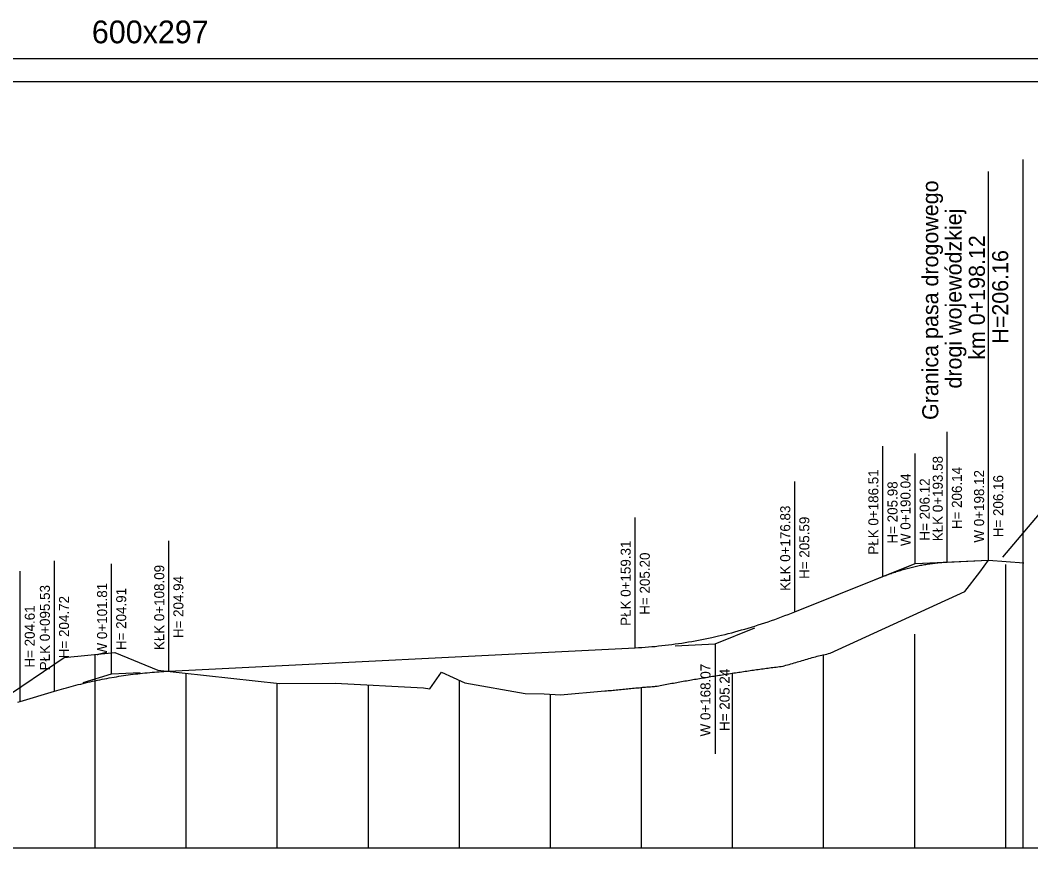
# Model space of a CAD drawing. Extents: x 6513080 to 6513380, y 6022307 to 6022459.
# Drawn here: x 6513209.5 to 6513320.4, y 6022367.8 to 6022459.5 of the extents above; entities that cross this region are included whole.
import ezdxf

# ---------------------------------------------------------------- set-up
doc = ezdxf.new("R2010")
doc.units = 0
for name, color, linetype in [('1', 7, 'Continuous'), ('42', 7, 'Continuous'), ('CONSTRUCTION_CLASS', 7, 'Continuous'), ('maxp_opisy', 7, 'Continuous'), ('maxp_ramka_2', 7, 'Continuous')]:
    doc.layers.add(name, color=color, linetype=linetype)

msp = doc.modelspace()

# ---------------------------------------------------------------- linework, layer by layer
for p, q in [((6513294.53, 6022394.49), (6513307.74, 6022399.78)), ((6513307.74, 6022399.78), (6513315.82, 6022400.17)), ((6513311.28, 6022399.95), (6513315.82, 6022400.17)), ((6513294.53, 6022394.49), (6513304.21, 6022398.37)), ((6513225.79, 6022387.98), (6513277.01, 6022390.55)), ((6513225.79, 6022387.98), (6513277.01, 6022390.55)), ((6513209.47, 6022384.65), (6513213.23, 6022385.78)), ((6513209.47, 6022384.65), (6513213.23, 6022385.78))]:
    msp.add_line(p, q)
for points in [[(6513304.21, 6022398.37), (6513304.36, 6022398.43), (6513304.51, 6022398.49), (6513304.65, 6022398.54), (6513304.8, 6022398.6), (6513304.95, 6022398.65), (6513305.1, 6022398.7), (6513305.24, 6022398.76), (6513305.39, 6022398.81), (6513305.54, 6022398.86), (6513305.68, 6022398.91), (6513305.83, 6022398.95), (6513305.98, 6022399), (6513306.13, 6022399.04), (6513306.27, 6022399.09), (6513306.42, 6022399.13), (6513306.57, 6022399.17), (6513306.71, 6022399.22), (6513306.86, 6022399.26), (6513307.01, 6022399.29), (6513307.16, 6022399.33), (6513307.3, 6022399.37), (6513307.45, 6022399.4), (6513307.6, 6022399.44), (6513307.89, 6022399.51), (6513308.04, 6022399.54), (6513308.19, 6022399.57), (6513308.33, 6022399.6), (6513308.48, 6022399.62), (6513308.63, 6022399.65), (6513308.78, 6022399.68), (6513308.92, 6022399.7), (6513309.07, 6022399.73), (6513309.22, 6022399.75), (6513309.36, 6022399.77), (6513309.51, 6022399.79), (6513309.66, 6022399.81), (6513309.81, 6022399.83), (6513309.95, 6022399.84), (6513310.1, 6022399.86), (6513310.25, 6022399.88), (6513310.39, 6022399.89), (6513310.54, 6022399.9), (6513310.69, 6022399.91), (6513310.84, 6022399.93), (6513310.98, 6022399.94), (6513311.13, 6022399.94), (6513311.28, 6022399.95)], [(6513277.01, 6022390.55), (6513277.38, 6022390.57), (6513277.74, 6022390.59), (6513278.11, 6022390.61), (6513278.47, 6022390.64), (6513278.84, 6022390.67), (6513279.2, 6022390.7), (6513279.57, 6022390.74), (6513279.93, 6022390.78), (6513280.3, 6022390.82), (6513280.66, 6022390.86), (6513281.03, 6022390.91), (6513281.39, 6022390.96), (6513281.76, 6022391.01), (6513282.12, 6022391.06), (6513282.49, 6022391.12), (6513282.85, 6022391.18), (6513283.22, 6022391.24), (6513283.58, 6022391.31), (6513283.95, 6022391.37), (6513284.31, 6022391.44), (6513284.68, 6022391.52), (6513285.04, 6022391.59), (6513285.41, 6022391.67), (6513286.14, 6022391.84), (6513286.5, 6022391.92), (6513286.87, 6022392.01), (6513287.23, 6022392.1), (6513287.6, 6022392.2), (6513287.96, 6022392.29), (6513288.33, 6022392.39), (6513288.69, 6022392.5), (6513289.06, 6022392.6), (6513289.42, 6022392.71), (6513289.79, 6022392.82), (6513290.15, 6022392.93), (6513290.52, 6022393.05), (6513290.88, 6022393.16), (6513291.25, 6022393.29), (6513291.61, 6022393.41), (6513291.98, 6022393.54), (6513292.34, 6022393.66), (6513292.71, 6022393.8), (6513293.07, 6022393.93), (6513293.44, 6022394.07), (6513293.8, 6022394.21), (6513294.17, 6022394.35), (6513294.53, 6022394.49)], [(6513277.01, 6022390.55), (6513277.38, 6022390.57), (6513277.74, 6022390.59), (6513278.11, 6022390.61), (6513278.47, 6022390.64), (6513278.84, 6022390.67), (6513279.2, 6022390.7), (6513279.57, 6022390.74), (6513279.93, 6022390.78), (6513280.3, 6022390.82), (6513280.66, 6022390.86), (6513281.03, 6022390.91), (6513281.39, 6022390.96), (6513281.76, 6022391.01), (6513282.12, 6022391.06), (6513282.49, 6022391.12), (6513282.85, 6022391.18), (6513283.22, 6022391.24), (6513283.58, 6022391.31), (6513283.95, 6022391.37), (6513284.31, 6022391.44), (6513284.68, 6022391.52), (6513285.04, 6022391.59), (6513285.41, 6022391.67), (6513286.14, 6022391.84), (6513286.5, 6022391.92), (6513286.87, 6022392.01), (6513287.23, 6022392.1), (6513287.6, 6022392.2), (6513287.96, 6022392.29), (6513288.33, 6022392.39), (6513288.69, 6022392.5), (6513289.06, 6022392.6), (6513289.42, 6022392.71), (6513289.79, 6022392.82), (6513290.15, 6022392.93), (6513290.52, 6022393.05), (6513290.88, 6022393.16), (6513291.25, 6022393.29), (6513291.61, 6022393.41), (6513291.98, 6022393.54), (6513292.34, 6022393.66), (6513292.71, 6022393.8), (6513293.07, 6022393.93), (6513293.44, 6022394.07), (6513293.8, 6022394.21), (6513294.17, 6022394.35), (6513294.53, 6022394.49)], [(6513213.23, 6022385.78), (6513213.49, 6022385.86), (6513213.75, 6022385.93), (6513214.01, 6022386.01), (6513214.27, 6022386.08), (6513214.54, 6022386.15), (6513214.8, 6022386.23), (6513215.06, 6022386.3), (6513215.32, 6022386.36), (6513215.58, 6022386.43), (6513215.84, 6022386.5), (6513216.11, 6022386.56), (6513216.37, 6022386.62), (6513216.63, 6022386.69), (6513216.89, 6022386.75), (6513217.15, 6022386.81), (6513217.41, 6022386.86), (6513217.68, 6022386.92), (6513217.94, 6022386.97), (6513218.2, 6022387.03), (6513218.46, 6022387.08), (6513218.72, 6022387.13), (6513218.98, 6022387.18), (6513219.25, 6022387.23), (6513219.77, 6022387.32), (6513220.03, 6022387.36), (6513220.29, 6022387.41), (6513220.55, 6022387.45), (6513220.82, 6022387.49), (6513221.08, 6022387.53), (6513221.34, 6022387.56), (6513221.6, 6022387.6), (6513221.86, 6022387.63), (6513222.12, 6022387.67), (6513222.39, 6022387.7), (6513222.65, 6022387.73), (6513222.91, 6022387.76), (6513223.17, 6022387.78), (6513223.43, 6022387.81), (6513223.69, 6022387.83), (6513223.96, 6022387.86), (6513224.22, 6022387.88), (6513224.48, 6022387.9), (6513224.74, 6022387.92), (6513225, 6022387.94), (6513225.26, 6022387.95), (6513225.53, 6022387.97), (6513225.79, 6022387.98)], [(6513213.23, 6022385.78), (6513213.49, 6022385.86), (6513213.75, 6022385.93), (6513214.01, 6022386.01), (6513214.27, 6022386.08), (6513214.54, 6022386.15), (6513214.8, 6022386.23), (6513215.06, 6022386.3), (6513215.32, 6022386.36), (6513215.58, 6022386.43), (6513215.84, 6022386.5), (6513216.11, 6022386.56), (6513216.37, 6022386.62), (6513216.63, 6022386.69), (6513216.89, 6022386.75), (6513217.15, 6022386.81), (6513217.41, 6022386.86), (6513217.68, 6022386.92), (6513217.94, 6022386.97), (6513218.2, 6022387.03), (6513218.46, 6022387.08), (6513218.72, 6022387.13), (6513218.98, 6022387.18), (6513219.25, 6022387.23), (6513219.77, 6022387.32), (6513220.03, 6022387.36), (6513220.29, 6022387.41), (6513220.55, 6022387.45), (6513220.82, 6022387.49), (6513221.08, 6022387.53), (6513221.34, 6022387.56), (6513221.6, 6022387.6), (6513221.86, 6022387.63), (6513222.12, 6022387.67), (6513222.39, 6022387.7), (6513222.65, 6022387.73), (6513222.91, 6022387.76), (6513223.17, 6022387.78), (6513223.43, 6022387.81), (6513223.69, 6022387.83), (6513223.96, 6022387.86), (6513224.22, 6022387.88), (6513224.48, 6022387.9), (6513224.74, 6022387.92), (6513225, 6022387.94), (6513225.26, 6022387.95), (6513225.53, 6022387.97), (6513225.79, 6022387.98)], [(6513209.21, 6022384.57), (6513209.47, 6022384.65)], [(6513209.21, 6022384.57), (6513209.47, 6022384.65)]]:
    msp.add_lwpolyline(points)
at = {"layer": '1'}
for p, q in [((6513305.98, 6022399.08), (6513307.74, 6022399.78)), ((6513307.74, 6022399.78), (6513309.51, 6022399.87)), ((6513315.82, 6022400.17), (6513319.69, 6022399.86)), ((6513317.7, 6022368.56), (6513317.7, 6022399.68)), ((6513285.77, 6022390.98), (6513290.15, 6022392.74)), ((6513307.7, 6022368.56), (6513307.7, 6022392.05)), ((6513281.39, 6022390.77), (6513285.77, 6022390.98)), ((6513217.7, 6022368.56), (6513217.7, 6022389.82)), ((6513297.7, 6022368.56), (6513297.7, 6022389.79)), ((6513216.37, 6022386.72), (6513219.51, 6022387.67)), ((6513219.51, 6022387.67), (6513222.65, 6022387.83)), ((6513227.7, 6022368.56), (6513227.7, 6022387.76)), ((6513287.7, 6022368.56), (6513287.7, 6022387.76)), ((6513237.7, 6022368.56), (6513237.7, 6022386.66)), ((6513247.7, 6022368.56), (6513247.7, 6022386.46)), ((6513257.7, 6022368.56), (6513257.7, 6022386.96)), ((6513277.7, 6022368.56), (6513277.7, 6022386.19)), ((6513267.7, 6022368.56), (6513267.7, 6022385.43)), ((6513217.7, 6022368.56), (6513217.7, 6022370.56)), ((6513227.7, 6022368.56), (6513227.7, 6022369.56)), ((6513237.7, 6022368.56), (6513237.7, 6022369.56)), ((6513247.7, 6022368.56), (6513247.7, 6022369.56)), ((6513257.7, 6022368.56), (6513257.7, 6022369.56)), ((6513267.7, 6022368.56), (6513267.7, 6022369.56)), ((6513277.7, 6022368.56), (6513277.7, 6022369.56)), ((6513287.7, 6022368.56), (6513287.7, 6022369.56)), ((6513297.7, 6022368.56), (6513297.7, 6022369.56)), ((6513307.7, 6022368.56), (6513307.7, 6022369.56)), ((6513317.7, 6022368.56), (6513317.7, 6022370.56)), ((6513117.7, 6022368.56), (6513327.7, 6022368.56))]:
    msp.add_line(p, q, dxfattribs=at)
msp.add_lwpolyline([(6513207.39, 6022384.79), (6513214.28, 6022389.47), (6513219.87, 6022390.04), (6513224.57, 6022388.1), (6513237.96, 6022386.63), (6513244.04, 6022386.65), (6513253.74, 6022386.15), (6513254.46, 6022386.02), (6513255.73, 6022387.88), (6513258.29, 6022386.69), (6513264.93, 6022385.53), (6513267.02, 6022385.47), (6513268.82, 6022385.37), (6513273.67, 6022385.81), (6513273.85, 6022385.82), (6513274.03, 6022385.84), (6513274.21, 6022385.85), (6513274.39, 6022385.87), (6513274.57, 6022385.89), (6513274.75, 6022385.9), (6513274.93, 6022385.92), (6513275.11, 6022385.94), (6513275.29, 6022385.95), (6513275.46, 6022385.97), (6513275.64, 6022385.99), (6513275.82, 6022386), (6513276, 6022386.02), (6513276.18, 6022386.04), (6513276.36, 6022386.06), (6513276.54, 6022386.07), (6513276.72, 6022386.09), (6513276.9, 6022386.11), (6513277.08, 6022386.13), (6513277.26, 6022386.14), (6513277.44, 6022386.16), (6513277.61, 6022386.18), (6513277.79, 6022386.2), (6513277.97, 6022386.22), (6513278.15, 6022386.23), (6513278.28, 6022386.25), (6513278.33, 6022386.25), (6513278.51, 6022386.26), (6513278.69, 6022386.27), (6513278.87, 6022386.28), (6513279.05, 6022386.29), (6513279.14, 6022386.29), (6513279.23, 6022386.31), (6513279.41, 6022386.34), (6513279.59, 6022386.38), (6513279.76, 6022386.41), (6513279.94, 6022386.44), (6513280.12, 6022386.48), (6513280.3, 6022386.51), (6513280.48, 6022386.54), (6513280.66, 6022386.58), (6513280.84, 6022386.61), (6513281.02, 6022386.64), (6513281.2, 6022386.67), (6513281.38, 6022386.71), (6513281.56, 6022386.74), (6513281.74, 6022386.77), (6513281.91, 6022386.8), (6513282.09, 6022386.83), (6513282.27, 6022386.87), (6513282.45, 6022386.9), (6513282.63, 6022386.93), (6513282.81, 6022386.96), (6513282.99, 6022386.99), (6513283.17, 6022387.02), (6513283.35, 6022387.05), (6513283.53, 6022387.08), (6513283.71, 6022387.11), (6513283.89, 6022387.14), (6513284.06, 6022387.17), (6513284.24, 6022387.2), (6513284.42, 6022387.23), (6513284.6, 6022387.26), (6513284.78, 6022387.29), (6513284.96, 6022387.32), (6513285.14, 6022387.35), (6513285.32, 6022387.38), (6513285.5, 6022387.41), (6513285.68, 6022387.44), (6513285.86, 6022387.47), (6513286.04, 6022387.5), (6513286.22, 6022387.53), (6513286.39, 6022387.55), (6513286.57, 6022387.58), (6513286.75, 6022387.61), (6513286.93, 6022387.64), (6513287.11, 6022387.67), (6513287.29, 6022387.69), (6513287.47, 6022387.72), (6513287.65, 6022387.75), (6513287.83, 6022387.78), (6513288.01, 6022387.8), (6513288.19, 6022387.83), (6513288.37, 6022387.86), (6513288.54, 6022387.88), (6513288.72, 6022387.91), (6513288.9, 6022387.94), (6513289.08, 6022387.96), (6513289.26, 6022387.99), (6513289.44, 6022388.01), (6513289.62, 6022388.04), (6513289.8, 6022388.07), (6513289.98, 6022388.09), (6513290.16, 6022388.12), (6513290.34, 6022388.14), (6513290.52, 6022388.17), (6513290.69, 6022388.19), (6513290.87, 6022388.22), (6513291.05, 6022388.24), (6513291.23, 6022388.26), (6513291.41, 6022388.29), (6513291.59, 6022388.31), (6513291.77, 6022388.34), (6513291.95, 6022388.36), (6513292.13, 6022388.38), (6513292.31, 6022388.41), (6513292.49, 6022388.43), (6513292.67, 6022388.45), (6513292.84, 6022388.47), (6513293.02, 6022388.5), (6513293.2, 6022388.52), (6513293.27, 6022388.53), (6513293.38, 6022388.56), (6513293.56, 6022388.62), (6513293.74, 6022388.67), (6513293.92, 6022388.72), (6513294.1, 6022388.78), (6513294.28, 6022388.83), (6513294.46, 6022388.88), (6513294.64, 6022388.94), (6513294.82, 6022388.99), (6513294.99, 6022389.04), (6513295.17, 6022389.09), (6513295.35, 6022389.15), (6513295.53, 6022389.2), (6513295.71, 6022389.25), (6513295.89, 6022389.3), (6513296.07, 6022389.35), (6513296.25, 6022389.41), (6513296.43, 6022389.46), (6513296.61, 6022389.51), (6513296.79, 6022389.56), (6513296.97, 6022389.61), (6513297.14, 6022389.66), (6513297.3, 6022389.7), (6513297.32, 6022389.71), (6513297.5, 6022389.75), (6513297.68, 6022389.78), (6513297.86, 6022389.82), (6513298.04, 6022389.86), (6513298.22, 6022389.9), (6513298.4, 6022389.94), (6513313.2, 6022396.72), (6513314.86, 6022398.86), (6513315.82, 6022400.17)], dxfattribs=at)
at = {"layer": '42'}
for p, q in [((6513319.62, 6022368.56), (6513319.62, 6022444.15)), ((6513315.82, 6022400.17), (6513315.82, 6022442.86)), ((6513311.28, 6022399.95), (6513311.28, 6022414.25)), ((6513304.21, 6022398.37), (6513304.21, 6022412.67)), ((6513307.74, 6022399.78), (6513307.74, 6022411.88)), ((6513315.82, 6022400.17), (6513315.82, 6022412.27)), ((6513294.53, 6022394.49), (6513294.53, 6022408.79)), ((6513323.46, 6022407.75), (6513317.33, 6022400.48)), ((6513277.01, 6022390.55), (6513277.01, 6022404.85)), ((6513225.79, 6022387.98), (6513225.79, 6022402.28)), ((6513213.23, 6022385.78), (6513213.23, 6022400.08)), ((6513219.51, 6022387.67), (6513219.51, 6022399.77)), ((6513311.28, 6022399.95), (6513315.82, 6022400.17)), ((6513209.47, 6022384.65), (6513209.47, 6022398.95)), ((6513294.53, 6022394.49), (6513304.21, 6022398.37)), ((6513285.77, 6022390.98), (6513285.77, 6022378.88)), ((6513225.79, 6022387.98), (6513277.01, 6022390.55)), ((6513209.47, 6022384.65), (6513213.23, 6022385.78))]:
    msp.add_line(p, q, dxfattribs=at)
for points in [[(6513304.21, 6022398.37), (6513304.36, 6022398.43), (6513304.51, 6022398.49), (6513304.65, 6022398.54), (6513304.8, 6022398.6), (6513304.95, 6022398.65), (6513305.1, 6022398.7), (6513305.24, 6022398.76), (6513305.39, 6022398.81), (6513305.54, 6022398.86), (6513305.68, 6022398.91), (6513305.83, 6022398.95), (6513305.98, 6022399), (6513306.13, 6022399.04), (6513306.27, 6022399.09), (6513306.42, 6022399.13), (6513306.57, 6022399.17), (6513306.71, 6022399.22), (6513306.86, 6022399.26), (6513307.01, 6022399.29), (6513307.16, 6022399.33), (6513307.3, 6022399.37), (6513307.45, 6022399.4), (6513307.6, 6022399.44), (6513307.89, 6022399.51), (6513308.04, 6022399.54), (6513308.19, 6022399.57), (6513308.33, 6022399.6), (6513308.48, 6022399.62), (6513308.63, 6022399.65), (6513308.78, 6022399.68), (6513308.92, 6022399.7), (6513309.07, 6022399.73), (6513309.22, 6022399.75), (6513309.36, 6022399.77), (6513309.51, 6022399.79), (6513309.66, 6022399.81), (6513309.81, 6022399.83), (6513309.95, 6022399.84), (6513310.1, 6022399.86), (6513310.25, 6022399.88), (6513310.39, 6022399.89), (6513310.54, 6022399.9), (6513310.69, 6022399.91), (6513310.84, 6022399.93), (6513310.98, 6022399.94), (6513311.13, 6022399.94), (6513311.28, 6022399.95)], [(6513277.01, 6022390.55), (6513277.38, 6022390.57), (6513277.74, 6022390.59), (6513278.11, 6022390.61), (6513278.47, 6022390.64), (6513278.84, 6022390.67), (6513279.2, 6022390.7), (6513279.57, 6022390.74), (6513279.93, 6022390.78), (6513280.3, 6022390.82), (6513280.66, 6022390.86), (6513281.03, 6022390.91), (6513281.39, 6022390.96), (6513281.76, 6022391.01), (6513282.12, 6022391.06), (6513282.49, 6022391.12), (6513282.85, 6022391.18), (6513283.22, 6022391.24), (6513283.58, 6022391.31), (6513283.95, 6022391.37), (6513284.31, 6022391.44), (6513284.68, 6022391.52), (6513285.04, 6022391.59), (6513285.41, 6022391.67), (6513286.14, 6022391.84), (6513286.5, 6022391.92), (6513286.87, 6022392.01), (6513287.23, 6022392.1), (6513287.6, 6022392.2), (6513287.96, 6022392.29), (6513288.33, 6022392.39), (6513288.69, 6022392.5), (6513289.06, 6022392.6), (6513289.42, 6022392.71), (6513289.79, 6022392.82), (6513290.15, 6022392.93), (6513290.52, 6022393.05), (6513290.88, 6022393.16), (6513291.25, 6022393.29), (6513291.61, 6022393.41), (6513291.98, 6022393.54), (6513292.34, 6022393.66), (6513292.71, 6022393.8), (6513293.07, 6022393.93), (6513293.44, 6022394.07), (6513293.8, 6022394.21), (6513294.17, 6022394.35), (6513294.53, 6022394.49)], [(6513213.23, 6022385.78), (6513213.49, 6022385.86), (6513213.75, 6022385.93), (6513214.01, 6022386.01), (6513214.27, 6022386.08), (6513214.54, 6022386.15), (6513214.8, 6022386.23), (6513215.06, 6022386.3), (6513215.32, 6022386.36), (6513215.58, 6022386.43), (6513215.84, 6022386.5), (6513216.11, 6022386.56), (6513216.37, 6022386.62), (6513216.63, 6022386.69), (6513216.89, 6022386.75), (6513217.15, 6022386.81), (6513217.41, 6022386.86), (6513217.68, 6022386.92), (6513217.94, 6022386.97), (6513218.2, 6022387.03), (6513218.46, 6022387.08), (6513218.72, 6022387.13), (6513218.98, 6022387.18), (6513219.25, 6022387.23), (6513219.77, 6022387.32), (6513220.03, 6022387.36), (6513220.29, 6022387.41), (6513220.55, 6022387.45), (6513220.82, 6022387.49), (6513221.08, 6022387.53), (6513221.34, 6022387.56), (6513221.6, 6022387.6), (6513221.86, 6022387.63), (6513222.12, 6022387.67), (6513222.39, 6022387.7), (6513222.65, 6022387.73), (6513222.91, 6022387.76), (6513223.17, 6022387.78), (6513223.43, 6022387.81), (6513223.69, 6022387.83), (6513223.96, 6022387.86), (6513224.22, 6022387.88), (6513224.48, 6022387.9), (6513224.74, 6022387.92), (6513225, 6022387.94), (6513225.26, 6022387.95), (6513225.53, 6022387.97), (6513225.79, 6022387.98)], [(6513209.21, 6022384.57), (6513209.47, 6022384.65)]]:
    msp.add_lwpolyline(points, dxfattribs=at)
at = {"layer": 'maxp_ramka_2'}
for points in [[(6513079.9, 6022455.24), (6513379.9, 6022455.24), (6513379.9, 6022306.74), (6513079.9, 6022306.74)], [(6513092.4, 6022309.24), (6513092.4, 6022452.74), (6513377.4, 6022452.74), (6513377.4, 6022309.24)]]:
    msp.add_lwpolyline(points, close=True, dxfattribs=at)

# ---------------------------------------------------------------- texts
at = {"layer": '42'}
for s, p in [('KŁK 0+193.58', (6513310.78, 6022402.24)), ('PŁK 0+186.51', (6513303.71, 6022400.77)), ('W 0+190.04', (6513307.24, 6022401.71)), ('H= 206.14', (6513312.88, 6022403.57)), ('W 0+198.12', (6513315.32, 6022402.09)), ('H= 206.16', (6513317.42, 6022402.68)), ('H= 205.98', (6513305.81, 6022401.99)), ('H= 206.12', (6513309.34, 6022402.31)), ('KŁK 0+176.83', (6513294.03, 6022396.79)), ('H= 205.59', (6513296.13, 6022398.11)), ('PŁK 0+159.31', (6513276.51, 6022392.95)), ('H= 205.20', (6513278.61, 6022394.17)), ('KŁK 0+108.09', (6513225.29, 6022390.28)), ('H= 204.94', (6513227.39, 6022391.6)), ('PŁK 0+095.53', (6513212.73, 6022388.07)), ('W 0+101.81', (6513219.01, 6022389.7)), ('H= 204.72', (6513214.83, 6022389.4)), ('H= 204.91', (6513221.11, 6022390.29)), ('H= 204.61', (6513211.07, 6022388.37)), ('W 0+168.07', (6513285.27, 6022380.81)), ('H= 205.24', (6513287.37, 6022381.41))]:
    msp.add_text(s, height=1.1, rotation=90, dxfattribs=at).set_placement(p)
at = {"layer": 'CONSTRUCTION_CLASS'}
msp.add_text('600x297', height=2.5, rotation=0.0002, dxfattribs=at).set_placement((6513217.34, 6022456.92))
at = {"layer": 'maxp_opisy'}
for s, p in [('Granica pasa drogowego ', (6513310.29, 6022415.56)), ('drogi wojewódzkiej', (6513312.85, 6022419.01)), ('km 0+198.12', (6513315.41, 6022422.17)), ('H=206.16', (6513317.97, 6022423.94))]:
    msp.add_text(s, height=1.76, rotation=90.0162, dxfattribs=at).set_placement(p)

doc.saveas('drawing.dxf')
